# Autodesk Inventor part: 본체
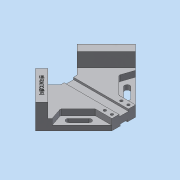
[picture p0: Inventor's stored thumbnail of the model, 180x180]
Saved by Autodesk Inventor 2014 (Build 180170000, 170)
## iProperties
Created: 2019-04
Part Number: 본체
Material: 알루미늄 6061
Document SubType Name: Modeling
Designer: 601-06
Density: 2.71 g/cm^3
Appearance: 알루미늄 - 평지
Mass: 603.568 g
Surface Area: 426.764 cm^2
Volume: 222.719 cm^3
Author: 601-06
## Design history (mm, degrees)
sketch "스케치4"
  geometry: L1 (-20, 0)-(0, 0); L2 (149.706, 0)-(114.35, -35.355); L3 (64.853, -84.853)-(0, -20); L4 (0, 0)-(0, -20); L5 (114.35, -35.355)-(93, -14.005); L6 (93, -14.005)-(93, 0); L7 (0, -20)-(-20, 0); L8 (114.35, -35.355)-(64.853, -84.853); L9 (93, 0)-(149.706, 0); L10 (0, 0)-(93, 0); L11 (93, 14.005)-(93, 0); L12 (114.35, 35.355)-(93, 14.005); L13 (114.35, 35.355)-(64.853, 84.853); L14 (64.853, 84.853)-(0, 20); L15 (0, 0)-(0, 20); 2 further points
  constraints: 30 end point, 12 perpendicular, 4 symmetric about line, 3 coincident, 3 horizontal
  dimensions: "d1" = 120 distance of L3.start L1.start; "d2" = 120 distance of L2.start L3.start; "d3" = 20 distance from line of L4 L1.start; "d5" = 93 distance between parallel lines of L4 L6; "d6" = 70 distance between parallel lines of L3 L5
extrude "돌출1" new body sketch "스케치4" distance "d7" = 18; taper "d8" = 0 deg
sketch "스케치5"
  geometry: L1 (-93, -14.005)-(-114.35, -35.355) reference; L2 (-114.35, -35.355)-(-64.853, -84.853) reference; L3 (-64.853, -84.853)-(0, -20) reference; L4 (0, 20)-(-64.853, 84.853) reference; L5 (-64.853, 84.853)-(-114.35, 35.355) reference; L6 (-114.35, 35.355)-(-93, 14.005) reference; L7 (-54.246, -74.246)-(-103.744, -24.749); L8 (-103.744, 24.749)-(-54.246, 74.246); 1 further point
  constraints: 4 end point, 4 point on line, 2 perpendicular
  dimensions: "d9" = 15 distance between parallel lines of L5 L8; "d10" = 15 distance between parallel lines of L2 L7
extrude "돌출2" join sketch "스케치5" distance "d11" = 24; taper "d12" = 0 deg
sketch "스케치6"
  geometry: L1 (-54.246, -74.246)-(0, -20) reference; L2 (0, -20)-(0, 20) reference; L3 (-93, 14.005)-(-93, -14.005) reference; L4 (-28.284, -20)-(-57.782, -49.497); L5 (-57.782, -49.497)-(-50.711, -70.711); L6 (0, -20)-(-28.284, -20); L7 (-114.35, -35.355)-(-64.853, -84.853) reference; 1 further point
  constraints: 6 end point, 2 point on line, 1 parallel, 1 perpendicular
  dimensions: "d13" = 20 distance between parallel lines of L4 L1; "d14" = 20 distance of L5.end L7.end; "d15" = 30 distance from line of L7 L4.end; "d16" = 20 distance from line of point (0, 0) L6
extrude "돌출3" cut sketch "스케치6" distance "d17" = 10; taper "d18" = 0 deg
sketch "스케치7"
  geometry: L1 (0, -20)-(-50.711, -70.711) reference; L2 (-26.669, -32.527)-(-43.64, -49.497); L3 (-29.851, -29.345)-(-46.822, -46.315); L4 (-40.458, -52.679)-(-23.487, -35.709); L5 (-114.35, -35.355)-(-64.853, -84.853) reference; A1 r 4.5 centre (-26.669, -32.527) between (-23.487, -35.709) and (-29.851, -29.345); A2 r 4.5 centre (-43.64, -49.497) between (-46.822, -46.315) and (-40.458, -52.679); 2 further points
  constraints: 8 end point, 4 point on circle, 4 tangent, 2 centre point, 2 parallel, 1 midpoint
  dimensions: "d19" = 9 distance between parallel lines of L3 L4; "d20" = 40 distance from line of L5 L2.end; "d21" = 24 distance of L2.start L2.end; "d22" = 10 distance between parallel lines of L1 L2
extrude "돌출4" cut sketch "스케치7" stored distance "d23" = 10; taper "d24" = 0 deg
sketch "스케치8"
  geometry: L1 (0, -20)-(0, 20) reference; C1 r 2.25 at (-6, -14); C2 r 2.25 at (-18, -14); 1 further point
  constraints: 2 centre point
  dimensions: "d25" = 4.5 diameter of C1; "d26" = 14 vertical distance of point (0, 0) C1.centre; "d27" = 6 distance from line of C1.centre L1; "d28" = 4.5 diameter of C2; "d29" = 14 vertical distance of point (0, 0) C2.centre; "d30" = 12 distance of C2.centre C1.centre
extrude "돌출5" cut sketch "스케치8" stored distance "d31" = 10; taper "d32" = 0 deg
sketch "스케치9"
  geometry: C1 r 2.25 at (-6, 14) reference; C2 r 2.25 at (-18, 14) reference; 1 further point
hole "구멍1" sketch "스케치9" at (-18, 14), (-6, 14) diameter "d33" = 8; stored, may be unused: countersink angle "d37" = 90 deg, drill point angle "d39" = 0 deg; dims "d34" = 6, "d35" = 4, "d36" = 2, "d38" = 10
sketch "스케치10"
  geometry: L1 (0, -20)-(0, 20) reference; L2 (-93, 14.005)-(-93, -14.005) reference; L3 (-93, -8)-(0, -8); L4 (0, -8)-(0, 8); L5 (0, 8)-(-93, 8); L6 (-93, 8)-(-93, -8); 1 further point
  constraints: 8 end point, 2 parallel, 2 point on line, 1 horizontal, 1 perpendicular
  dimensions: "d40" = 16 distance between parallel lines of L3 L5; "d41" = 8 distance from line of L5 point (0, 0)
extrude "돌출6" cut sketch "스케치10" distance "d42" = 3.5; taper "d43" = 0 deg
sketch "스케치11"
  geometry: L1 (0, 20)-(0, -20) reference; L2 (-93, -14.005)-(-93, 14.005) reference; L3 (-93, 6)-(0, 6); L4 (0, 6)-(0, -6); L5 (0, -6)-(-93, -6); L6 (-93, -6)-(-93, 6); 1 further point
  constraints: 8 end point, 2 parallel, 2 point on line, 1 horizontal, 1 perpendicular
  dimensions: "d44" = 12 distance between parallel lines of L3 L5; "d45" = 6 distance from line of point (0, 0) L5
extrude "돌출7" cut sketch "스케치11" distance "d46" = 3; taper "d47" = 0 deg
sketch "스케치12"
  geometry: L1 (-114.35, -35.355)-(-64.853, -84.853) reference; L2 (-64.853, -84.853)-(-54.246, -74.246) reference; 2 further points
  constraints: 1 other
  dimensions: "d48" = 35 distance from line of L2 point (-84.298, -54.801); "d50" = 7.5 distance from line of L1 point (-84.298, -54.801)
feature "엠보싱1" sketch "스케치12" dims "d3" = 20, "d51" = 0.5, "d52" = 0
fillet "모깎기1" dims "d53" = 3
node "솔리드1"
mirror "대칭1"
mirror "대칭2"
